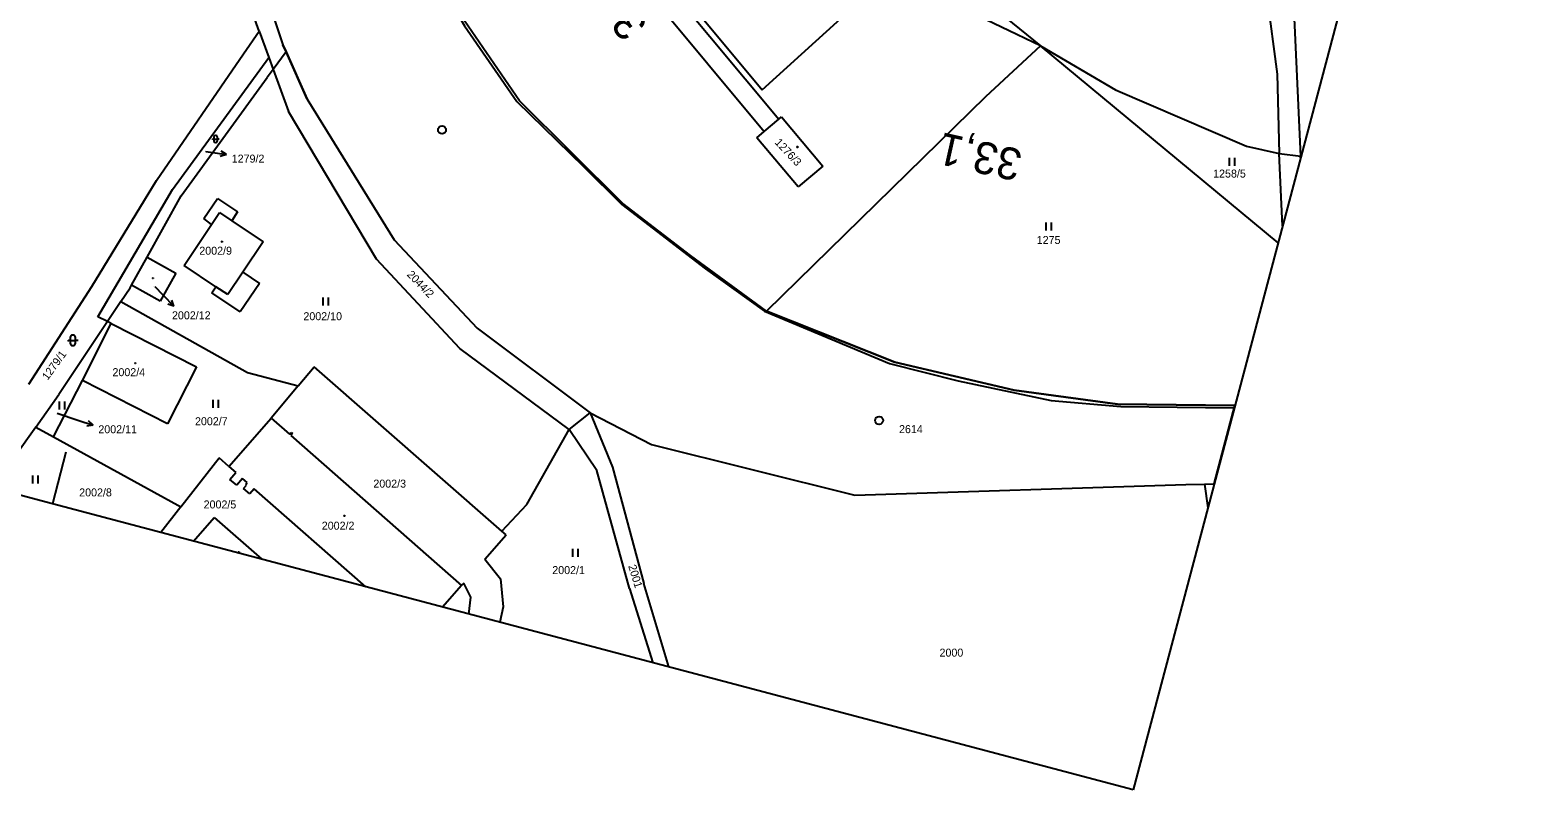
# Model space of a CAD drawing. Extents: x -805011 to -803920, y -1150790 to -1150234.
# Drawn here: x -804203.4 to -803920.3, y -1150790.1 to -1150647.5 of the extents above; entities that cross this region are included whole.
import ezdxf

# ---------------------------------------------------------------- set-up
doc = ezdxf.new("R2010")
doc.units = 0
for name, color, linetype in [('Default', 7, 'Continuous'), ('formát', 7, 'Continuous'), ('kilometráž - vrstava 7', 7, 'Continuous'), ('kn_celek - Cisla parcel pomocna', 7, 'Continuous'), ('kn_celek - Cisla pozemkovych parcel', 7, 'Continuous'), ('kn_celek - Cisla stavebnich parcel', 7, 'Continuous'), ('kn_celek - Hranice parcel', 7, 'Continuous'), ('kn_celek - Vnitrni kresby', 7, 'Continuous'), ('kn_celek - Znacky budov', 7, 'Continuous'), ('kn_celek - Znacky kultur', 7, 'Continuous'), ('plochy - SZDC', 7, 'Continuous'), ('PSR_C2_2_trasa_Vimperk - Kabelová trasa', 7, 'Continuous')]:
    doc.layers.add(name, color=color, linetype=linetype)

# ---------------------------------------------------------------- blocks, each defined once
blk = doc.blocks.new('306')
at = {"layer": 'Default'}
for p, q in [((-5.2, 0), (-5.2, 15)), ((4.8, 0), (4.8, 15))]:
    blk.add_line(p, q, dxfattribs=at)
blk = doc.blocks.new('316')
at = {"layer": 'Default'}
for p, q in [((-8.3, 10), (-10, 8.1)), ((-5, 10), (-8.3, 10)), ((-5, 15.5), (-5, 4.5)), ((-5, 10), (5, 10)), ((0.5, 20), (-0.5, 20)), ((-0.5, 0), (0.5, 0)), ((5, 4.5), (5, 15.5)), ((10, 10), (5, 10))]:
    blk.add_line(p, q, dxfattribs=at)
for centre, start, end in [((-0.5, 15.5), 90, 180), ((-0.5, 4.5), 180, 270), ((0.5, 15.5), 0, 90), ((0.5, 4.5), 270, 0)]:
    blk.add_arc(centre, 4.5, start, end, dxfattribs=at)
blk = doc.blocks.new('402')
at = {"layer": 'Default'}
for p, q in [((-0.8, 0.8), (0.7, 0.8)), ((-0.8, 0.8), (-0.8, -0.7)), ((0.7, 0.8), (0.7, -0.7)), ((0.7, -0.7), (-0.8, -0.7))]:
    blk.add_line(p, q, dxfattribs=at)
blk = doc.blocks.new('Z61')
at = {"layer": 'Default'}
for p, q in [((0, 0), (30, 0)), ((30, 0), (19.2, 5.3)), ((30, 0), (19.2, -5.3))]:
    blk.add_line(p, q, dxfattribs=at)

msp = doc.modelspace()

# ---------------------------------------------------------------- linework, layer by layer
at = {"layer": 'formát'}
for p, q in [((-803920.28, -1150503.02), (-803996.25, -1150790.14)), ((-804199.27, -1150736.42), (-804402.28, -1150682.7)), ((-804196.71, -1150726.75), (-804199.27, -1150736.42)), ((-804196.71, -1150726.75), (-804199.27, -1150736.42)), ((-803996.25, -1150790.14), (-804199.27, -1150736.42))]:
    msp.add_line(p, q, dxfattribs=at)
at = {"layer": 'kilometráž - vrstava 7'}
for centre in [(-804126.09, -1150666.21), (-804043.99, -1150720.76)]:
    msp.add_circle(centre, 0.75, dxfattribs=at)
at = {"layer": 'kn_celek - Cisla parcel pomocna'}
for p, q in [((-804170.43, -1150670.28), (-804169.55, -1150670.41)), ((-804180.05, -1150695.62), (-804178.54, -1150697.17)), ((-804198.35, -1150719.41), (-804194.47, -1150720.71))]:
    msp.add_line(p, q, dxfattribs=at)
at = {"layer": 'kn_celek - Hranice parcel'}
for p, q in [((-804152.05, -1150554.87), (-804065.98, -1150658.69)), ((-804146.64, -1150563.54), (-804062.82, -1150664.2)), ((-804149.4, -1150565.85), (-804065.57, -1150666.5)), ((-803964.82, -1150671.1), (-803968.67, -1150586.34)), ((-804160.41, -1150647.65), (-804175.13, -1150607.01)), ((-804166.92, -1150617.84), (-804155.97, -1150650.2)), ((-803971.93, -1150635.48), (-803969.24, -1150655.71)), ((-804026.54, -1150639.97), (-804013.68, -1150650.38)), ((-804111.51, -1150660.72), (-804123.96, -1150642.72)), ((-804013.68, -1150650.38), (-804028.35, -1150643.39)), ((-804065.98, -1150658.69), (-804051.16, -1150645.3)), ((-804163.36, -1150651.92), (-804160.41, -1150647.65)), ((-804160.41, -1150647.65), (-804158.62, -1150652.6)), ((-804179.73, -1150675.67), (-804163.36, -1150651.92)), ((-804176.72, -1150677.38), (-804158.62, -1150652.6)), ((-804158.62, -1150652.6), (-804157.81, -1150654.86)), ((-804155.38, -1150651.53), (-804157.81, -1150654.86)), ((-804155.38, -1150651.53), (-804155.97, -1150650.2)), ((-804151.42, -1150660.42), (-804155.38, -1150651.53)), ((-804013.68, -1150650.38), (-804024.02, -1150660)), ((-804013.68, -1150650.38), (-803999.62, -1150658.69)), ((-803969.07, -1150687.41), (-804013.68, -1150650.38)), ((-804157.81, -1150654.86), (-804158.91, -1150656.37)), ((-804157.81, -1150654.86), (-804154.95, -1150662.75)), ((-804175.1, -1150678.56), (-804158.91, -1150656.37)), ((-803969.24, -1150655.71), (-803968.89, -1150670.61)), ((-804151.42, -1150660.42), (-804135.09, -1150686.84)), ((-804092.1, -1150680), (-804111.51, -1150660.72)), ((-804024.02, -1150660), (-804065.16, -1150700.21)), ((-803999.62, -1150658.69), (-803974.99, -1150669.28)), ((-804138.42, -1150690.47), (-804154.95, -1150662.75)), ((-804062.82, -1150664.2), (-804062.31, -1150663.77)), ((-804062.31, -1150663.77), (-804054.58, -1150673.04)), ((-804066.95, -1150667.66), (-804065.57, -1150666.5)), ((-804065.57, -1150666.5), (-804062.82, -1150664.2)), ((-804059.21, -1150676.92), (-804066.95, -1150667.66)), ((-803974.99, -1150669.28), (-803968.89, -1150670.61)), ((-803968.89, -1150670.61), (-803964.82, -1150671.1)), ((-803968.23, -1150684.23), (-803968.89, -1150670.61)), ((-803964.84, -1150671.42), (-803964.82, -1150671.1)), ((-804054.58, -1150673.04), (-804059.21, -1150676.92)), ((-804191.87, -1150695.58), (-804179.73, -1150675.67)), ((-804190.7, -1150701.29), (-804176.72, -1150677.38)), ((-804181.49, -1150690.09), (-804175.1, -1150678.56)), ((-804170.85, -1150682.82), (-804168.27, -1150679.06)), ((-804168.27, -1150679.06), (-804164.47, -1150681.58)), ((-804079.43, -1150689.81), (-804092.1, -1150680)), ((-804169.4, -1150683.99), (-804170.85, -1150682.82)), ((-804164.47, -1150681.58), (-804165.58, -1150683.25)), ((-804165.58, -1150683.25), (-804159.65, -1150687.19)), ((-804174.53, -1150691.66), (-804169.4, -1150683.99)), ((-804159.65, -1150687.19), (-804163.49, -1150692.94)), ((-804135.09, -1150686.84), (-804119.46, -1150703.45)), ((-804184.41, -1150695.36), (-804181.49, -1150690.09)), ((-804181.49, -1150690.09), (-804176.1, -1150693.11)), ((-804168.55, -1150695.66), (-804174.53, -1150691.66)), ((-804122.73, -1150707.27), (-804138.42, -1150690.47)), ((-804065.16, -1150700.21), (-804079.43, -1150689.81)), ((-804176.1, -1150693.11), (-804179.05, -1150698.36)), ((-804160.38, -1150695.02), (-804163.97, -1150700.37)), ((-804163.49, -1150692.94), (-804160.38, -1150695.02)), ((-804203.66, -1150713.94), (-804191.87, -1150695.58)), ((-804186.38, -1150698.4), (-804184.67, -1150695.83)), ((-804184.67, -1150695.83), (-804184.41, -1150695.36)), ((-804179.05, -1150698.36), (-804184.41, -1150695.36)), ((-804169.29, -1150696.77), (-804168.55, -1150695.66)), ((-804163.97, -1150700.37), (-804169.29, -1150696.77)), ((-804186.38, -1150698.4), (-804188.91, -1150702.2)), ((-804186.38, -1150698.4), (-804162.59, -1150711.79)), ((-804065.16, -1150700.21), (-804041.05, -1150709.83)), ((-804188.91, -1150702.2), (-804198.04, -1150715.91)), ((-804193.64, -1150713.24), (-804188.2, -1150702.56)), ((-804188.91, -1150702.2), (-804190.7, -1150701.29)), ((-804188.2, -1150702.56), (-804188.91, -1150702.2)), ((-804188.2, -1150702.56), (-804172.18, -1150710.68)), ((-804119.46, -1150703.45), (-804098.25, -1150719.35)), ((-804102.23, -1150722.48), (-804122.73, -1150707.27)), ((-804172.18, -1150710.68), (-804177.63, -1150721.4)), ((-804162.59, -1150711.79), (-804153.08, -1150714.27)), ((-804153.08, -1150714.27), (-804150.08, -1150710.67)), ((-804114.86, -1150741.53), (-804150.08, -1150710.67)), ((-804041.05, -1150709.83), (-804018.63, -1150715.09)), ((-804199.04, -1150723.85), (-804193.64, -1150713.24)), ((-804177.63, -1150721.4), (-804193.64, -1150713.24)), ((-804153.08, -1150714.27), (-804158.15, -1150720.35)), ((-804202.38, -1150722.01), (-804198.04, -1150715.91)), ((-804018.63, -1150715.09), (-803999.22, -1150717.72)), ((-803999.22, -1150717.72), (-803977.16, -1150717.98)), ((-804166.11, -1150729.42), (-804158.15, -1150720.35)), ((-804158.15, -1150720.35), (-804154.73, -1150723.35)), ((-804102.23, -1150722.48), (-804098.25, -1150719.35)), ((-804098.25, -1150719.35), (-804094.06, -1150729.52)), ((-804098.25, -1150719.35), (-804086.77, -1150725.31)), ((-804202.38, -1150722.01), (-804210.52, -1150733.44)), ((-804202.38, -1150722.01), (-804199.04, -1150723.85)), ((-804154.73, -1150723.35), (-804154.44, -1150723.02)), ((-804154.19, -1150723.24), (-804154.48, -1150723.57)), ((-804154.44, -1150723.02), (-804154.19, -1150723.24)), ((-804110.16, -1150736.56), (-804102.23, -1150722.48)), ((-804096.98, -1150730.19), (-804102.23, -1150722.48)), ((-804199.04, -1150723.85), (-804175.72, -1150736.7)), ((-804154.48, -1150723.57), (-804122.41, -1150751.76)), ((-804086.77, -1150725.31), (-804048.58, -1150734.81)), ((-804175.17, -1150737), (-804167.95, -1150727.76)), ((-804166.11, -1150729.42), (-804167.95, -1150727.76)), ((-804166.11, -1150729.42), (-804164.8, -1150730.57)), ((-804165.91, -1150731.83), (-804164.8, -1150730.57)), ((-804164.64, -1150732.94), (-804165.91, -1150731.83)), ((-804163.53, -1150731.68), (-804164.64, -1150732.94)), ((-804162.67, -1150732.44), (-804163.53, -1150731.68)), ((-804090.85, -1150752.33), (-804096.98, -1150730.19)), ((-804094.06, -1150729.52), (-804088.18, -1150751.38)), ((-804163.34, -1150733.54), (-804162.78, -1150732.9)), ((-804162.19, -1150734.56), (-804163.34, -1150733.54)), ((-804162.95, -1150732.75), (-804162.67, -1150732.44)), ((-804162.78, -1150732.9), (-804162.95, -1150732.75)), ((-804161.35, -1150733.6), (-804162.19, -1150734.56)), ((-804140.41, -1150751.99), (-804161.35, -1150733.6)), ((-804048.58, -1150734.81), (-803986.36, -1150732.8)), ((-803986.36, -1150732.8), (-803982.91, -1150732.74)), ((-803982.91, -1150732.74), (-803981.05, -1150732.7)), ((-803982.91, -1150732.74), (-803982.24, -1150737.18)), ((-804175.17, -1150737), (-804178.92, -1150741.8)), ((-804175.72, -1150736.7), (-804175.17, -1150737)), ((-804114.86, -1150741.53), (-804110.16, -1150736.56)), ((-804172.74, -1150743.44), (-804168.86, -1150739.02)), ((-804168.86, -1150739.02), (-804159.91, -1150746.83)), ((-804118.04, -1150746.82), (-804114.02, -1150742.27)), ((-804114.02, -1150742.27), (-804114.86, -1150741.53)), ((-804118.04, -1150746.82), (-804115.12, -1150750.53)), ((-804122.01, -1150751.31), (-804122.41, -1150751.76)), ((-804120.67, -1150753.94), (-804122.01, -1150751.31)), ((-804115.12, -1150750.53), (-804114.63, -1150755.8)), ((-804083.48, -1150767.06), (-804088.18, -1150751.38)), ((-804122.41, -1150751.76), (-804125.98, -1150755.81)), ((-804121.03, -1150757.12), (-804120.67, -1150753.94)), ((-804090.85, -1150752.33), (-804086.47, -1150766.27)), ((-804114.63, -1150755.8), (-804115.22, -1150758.66))]:
    msp.add_line(p, q, dxfattribs=at)
at = {"layer": 'kn_celek - Vnitrni kresby'}
for p, q in [((-804169.4, -1150683.99), (-804167.88, -1150681.71)), ((-804167.88, -1150681.71), (-804165.58, -1150683.25)), ((-804163.49, -1150692.94), (-804166.29, -1150697.13)), ((-804166.29, -1150697.13), (-804168.55, -1150695.66))]:
    msp.add_line(p, q, dxfattribs=at)
at = {"layer": 'plochy - SZDC'}
for p, q in [((-804166.92, -1150617.84), (-804155.97, -1150650.2)), ((-804111.51, -1150660.72), (-804123.96, -1150642.72)), ((-804155.97, -1150650.2), (-804155.38, -1150651.53)), ((-804155.38, -1150651.53), (-804151.42, -1150660.42)), ((-804151.42, -1150660.42), (-804135.09, -1150686.84)), ((-804092.1, -1150680), (-804111.51, -1150660.72)), ((-804079.43, -1150689.81), (-804092.1, -1150680)), ((-804135.09, -1150686.84), (-804119.46, -1150703.45)), ((-804065.16, -1150700.21), (-804079.43, -1150689.81)), ((-804041.05, -1150709.83), (-804065.16, -1150700.21)), ((-804119.46, -1150703.45), (-804098.25, -1150719.35)), ((-804018.63, -1150715.09), (-804041.05, -1150709.83)), ((-803999.22, -1150717.72), (-804018.63, -1150715.09)), ((-803977.16, -1150717.98), (-803999.22, -1150717.72)), ((-804098.25, -1150719.35), (-804086.77, -1150725.31)), ((-803981.05, -1150732.7), (-803977.16, -1150717.98)), ((-804086.77, -1150725.31), (-804048.58, -1150734.81)), ((-804048.58, -1150734.81), (-803986.36, -1150732.8)), ((-803986.36, -1150732.8), (-803982.91, -1150732.74)), ((-803982.91, -1150732.74), (-803981.05, -1150732.7))]:
    msp.add_line(p, q, dxfattribs=at)
at = {"layer": 'PSR_C2_2_trasa_Vimperk - Kabelová trasa'}
for points in [[(-804211.94, -1150528.21), (-804207.53, -1150523.61), (-804196.77, -1150533.52), (-804182.83, -1150549.06), (-804177, -1150556.4), (-804170.6, -1150565.5), (-804165.46, -1150573.1), (-804159.32, -1150583.6), (-804148.34, -1150601.45), (-804139.82, -1150616.03), (-804133.21, -1150627.36), (-804121.85, -1150646.68), (-804112.03, -1150660.85), (-804099.51, -1150673.08)], [(-804099.51, -1150673.08), (-804092.3, -1150680.21), (-804076.61, -1150692.29), (-804065.52, -1150700.21), (-804042.05, -1150710.07), (-804029.14, -1150713.3), (-804011.66, -1150716.99), (-803998.6, -1150718.16), (-803977.42, -1150718.41), (-803977.26, -1150718.37)]]:
    msp.add_lwpolyline(points, dxfattribs=at)

# ---------------------------------------------------------------- block references
at = {"layer": 'kn_celek - Cisla parcel pomocna', "xscale": 0.1, "yscale": 0.10000000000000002}
for p, rotation in [((-804169.55, -1150670.41), -8.275949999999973), ((-804178.54, -1150697.17), -45.627839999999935), ((-804194.47, -1150720.71), -18.58823999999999)]:
    msp.add_blockref('Z61', p, dxfattribs=dict(at, rotation=rotation))
at = {"layer": 'kn_celek - Znacky budov', "xscale": 0.1, "yscale": 0.10000000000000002}
for p in [(-804059.35, -1150669.41), (-804167.45, -1150687.19), (-804180.41, -1150694.03), (-804183.72, -1150710.01), (-804144.43, -1150738.68), (-804164.28, -1150745.55)]:
    msp.add_blockref('402', p, dxfattribs=at)
at = {"layer": 'kn_celek - Znacky kultur'}
for name, p, xscale, yscale in [('316', (-804168.61, -1150668.58), 0.067, 0.067), ('306', (-803977.66, -1150672.95), 0.1, 0.10000000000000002), ('306', (-804012.07, -1150685.07), 0.1, 0.10000000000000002), ('306', (-804147.88, -1150699.18), 0.1, 0.10000000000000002), ('316', (-804195.42, -1150706.72), 0.1, 0.10000000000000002), ('306', (-804197.43, -1150718.69), 0.1, 0.10000000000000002), ('306', (-804168.52, -1150718.42), 0.1, 0.10000000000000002), ('306', (-804202.42, -1150732.63), 0.1, 0.10000000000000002), ('306', (-804101.02, -1150746.37), 0.1, 0.10000000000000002)]:
    msp.add_blockref(name, p, dxfattribs=dict(at, xscale=xscale, yscale=yscale))

# ---------------------------------------------------------------- texts
at = {"layer": 'kilometráž - vrstava 7'}
for s, rotation, p in [('33,2', 128.139, (-804087.18, -1150646.31)), ('33,1', 167.4012, (-804016.8, -1150670.05))]:
    msp.add_text(s, height=6, rotation=rotation, dxfattribs=at).set_placement(p)
at = {"layer": 'kn_celek - Cisla parcel pomocna'}
for s, p in [('1279/2', (-804165.58, -1150672.34)), ('2002/12', (-804176.8, -1150701.77)), ('2002/11', (-804190.63, -1150723.17))]:
    msp.add_text(s, height=1.5, dxfattribs=at).set_placement(p)
at = {"layer": 'kn_celek - Cisla pozemkovych parcel'}
for s, height, rotation, p in [('1279/2', 0.1, 53.2111, (-804170.62, -1150670.47)), ('2044/2', 1.5, 314.1, (-804132.79, -1150693.47)), ('1279/1', 1.5, 54, (-804200.15, -1150713.31)), ('2001', 1.5, 287.1, (-804091.13, -1150748.11))]:
    msp.add_text(s, height=height, rotation=rotation, dxfattribs=at).set_placement(p)
for s, height, p in [('1258/5', 1.5, (-803981.26, -1150675.15)), ('1275', 1.5, (-804014.39, -1150687.62)), ('2002/10', 1.5, (-804152.12, -1150701.94)), ('2002/11', 0.1, (-804198.35, -1150719.38)), ('2002/7', 1.5, (-804172.48, -1150721.66)), ('2614', 1.5, (-804040.26, -1150723.15)), ('2002/3', 1.5, (-804138.98, -1150733.38)), ('2002/8', 1.5, (-804194.23, -1150735.03)), ('2002/5', 1.5, (-804170.86, -1150737.29)), ('2002/1', 1.5, (-804105.38, -1150749.62)), ('2000', 1.5, (-804032.65, -1150765.12))]:
    msp.add_text(s, height=height, dxfattribs=at).set_placement(p)
at = {"layer": 'kn_celek - Cisla stavebnich parcel'}
msp.add_text('1276/3', height=1.5, rotation=313.189, dxfattribs=at).set_placement((-804063.7, -1150668.65))
for s, height, p in [('2002/9', 1.5, (-804171.67, -1150689.64)), ('2002/12', 0.1, (-804180.36, -1150695.59)), ('2002/4', 1.5, (-804187.98, -1150712.45)), ('2002/2', 1.5, (-804148.67, -1150741.28))]:
    msp.add_text(s, height=height, dxfattribs=at).set_placement(p)

doc.saveas('drawing.dxf')
